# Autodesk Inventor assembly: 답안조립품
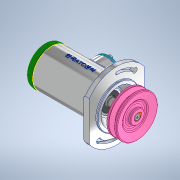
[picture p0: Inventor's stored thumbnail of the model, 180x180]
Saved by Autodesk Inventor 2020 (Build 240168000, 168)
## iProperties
Created: 2022-05
Part Number: 답안조립품
Document SubType Name: Assembly
Designer: Student
Author: Student
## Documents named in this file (16)
- C:\Users\Student\Desktop\720506V1023\답안조립품.iam
- C:\Users\Student\Desktop\720506V1023\본체.ipt
- C:\Users\Student\Desktop\720506V1023\사이드 커버.ipt
- 사이드 커버.ipt
- C:\Users\Student\Desktop\720506V1023\베어링 6202.ipt
- C:\Users\Student\Desktop\720506V1023\멈춤링 15 x 1.ipt
- C:\Users\Student\Desktop\720506V1023\멈춤링 35 x 1.6.ipt
- C:\Users\Student\Desktop\720506V1023\오일 실 15 x 30 x 7.ipt
- C:\Users\Student\Desktop\720506V1023\축.ipt
- C:\Users\Student\Desktop\720506V1023\와셔 10 x 21.ipt
- C:\Users\Student\Desktop\720506V1023\너트 M10.ipt
- C:\Users\Student\Desktop\720506V1023\개스킷.ipt
- C:\Users\Student\Desktop\720506V1023\키 4 x 4.ipt
- C:\Users\Student\Desktop\720506V1023\V-벨트풀리.ipt
- C:\Users\Student\Desktop\720506V1023\탑 커버.ipt
- C:\Users\Student\Desktop\720506V1023\볼트 M4 x 10.ipt
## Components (4 placed, 3 different names)
1. 개스킷:1
2. V-벨트풀리:1
3. ISO 4017 M4 x 10:1
4. ISO 4017 M4 x 10:2
